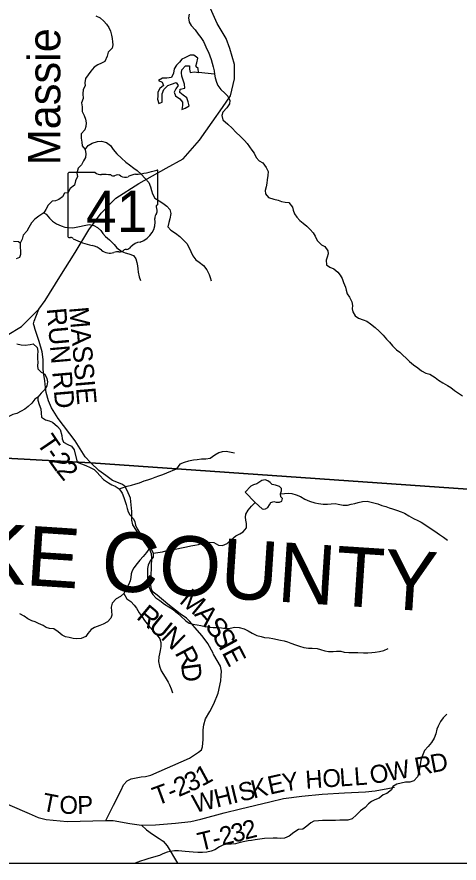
# Model space of a CAD drawing. Extents: x -139 to 835, y 0 to 440.
# Drawn here: x 426.3 to 470.9, y 185.1 to 270.4 of the extents above; entities that cross this region are included whole.
import ezdxf

# ---------------------------------------------------------------- set-up
doc = ezdxf.new("R2010")
doc.units = 0
for name, color, linetype in [('Default', 7, 'Continuous'), ('GM_X_County_Road', 7, 'Continuous'), ('GM_X_County_Road_Text', 7, 'Continuous'), ('GM_X_County_Text', 7, 'Continuous'), ('GM_X_Minor_Lake', 7, 'Continuous'), ('GM_X_Minor_River', 7, 'Continuous'), ('GM_X_Minor_River_Text', 7, 'Continuous'), ('GM_X_State_Location', 7, 'Continuous'), ('GM_X_State_Route', 7, 'Continuous'), ('GM_X_State_Shield', 7, 'Continuous'), ('GM_X_Township_Road', 7, 'Continuous'), ('GM_X_Township_Road_Text', 7, 'Continuous'), ('SH_Cut_Line', 7, 'Continuous')]:
    doc.layers.add(name, color=color, linetype=linetype)

msp = doc.modelspace()

# ---------------------------------------------------------------- linework, layer by layer
at = {"layer": 'Default'}
msp.add_lwpolyline([(373.24, 306.128), (373.24, 228.621), (390.412, 227.867), (402.968, 227.036), (407.389, 226.858), (433.728, 225.419), (479.461, 222.215), (494.743, 221.147), (512.652, 220.106), (533.705, 218.461), (553.865, 217.083)], dxfattribs=at)
msp.add_lwpolyline([(373.24, 228.621), (373.24, 185.075), (509.507, 185.075), (512.652, 220.106), (494.743, 221.147), (479.461, 222.215), (433.728, 225.419), (407.389, 226.858), (402.968, 227.036), (390.412, 227.867)], close=True, dxfattribs=at)
at = {"layer": 'GM_X_County_Road'}
msp.add_lwpolyline([(407.729, 190.508), (416.734, 193.08), (418.79, 193.617), (419.041, 193.654), (419.453, 193.54), (427.529, 190.066), (428.437, 189.666), (429.238, 189.452), (431.361, 189.276), (435.253, 189.374), (435.985, 189.354), (437.671, 189.078), (438.839, 188.895), (439.339, 188.429), (439.97, 187.993), (440.642, 187.567), (441.046, 187.285), (441.426, 186.8), (442.484, 185.075)], dxfattribs=at)
at = {"layer": 'GM_X_Minor_Lake'}
for points in [[(444.361, 265.332), (444.319, 265.378), (444.441, 265.737), (444.526, 266.204), (444.112, 266.485), (443.746, 266.489), (443.234, 266.231), (442.906, 266.102), (442.693, 265.793), (442.388, 265.484), (442.148, 265.115), (442.064, 264.684), (441.888, 264.254), (441.405, 264.188), (440.974, 264.169), (440.553, 263.957), (440.929, 263.773), (441.068, 263.436), (440.686, 263.152), (440.511, 262.758), (440.492, 262.362), (440.462, 262.063), (440.6, 261.641), (440.928, 261.769), (440.947, 262.237), (440.939, 262.585), (441.102, 263.039), (441.512, 263.442), (441.892, 263.582), (442.351, 263.745), (442.556, 263.443), (442.303, 263.109), (442.142, 262.763), (442.294, 262.39), (442.707, 262.097), (442.977, 261.746), (442.985, 261.41), (442.928, 261.015), (443.256, 261.155), (443.651, 261.39), (443.565, 261.799), (443.414, 262.209), (443.052, 262.465), (442.716, 262.745), (442.747, 263.056), (443.205, 263.183), (443.184, 263.567), (443.059, 263.965), (442.908, 264.375), (442.886, 264.699), (442.917, 265.022), (443.275, 265.414), (443.693, 265.434), (443.688, 265.074), (443.775, 264.761), (444.18, 264.804), (444.61, 264.751), (444.563, 265.148)], [(444.563, 265.148), (444.361, 265.332)], [(450.313, 221.401), (451.007, 220.778), (451.163, 220.73), (451.36, 220.79), (451.608, 220.911), (451.752, 221.187), (451.909, 221.403), (452.183, 221.511), (452.445, 221.452), (452.759, 221.464), (453.02, 221.548), (453.059, 221.813), (452.915, 221.992), (452.876, 222.293), (452.981, 222.605), (452.981, 222.833), (452.758, 223.025), (452.353, 223.144), (452.039, 223.24), (451.817, 223.42), (451.594, 223.6), (451.307, 223.696), (450.993, 223.635), (450.797, 223.503), (450.47, 223.31), (450.143, 223.178), (449.882, 223.058), (449.319, 222.469)], [(449.319, 222.469), (450.313, 221.401)]]:
    msp.add_lwpolyline(points, dxfattribs=at)
at = {"layer": 'GM_X_Minor_River'}
for points in [[(434.234, 270.473), (434.687, 270.252), (435.062, 269.936), (435.332, 269.633), (435.549, 269.294), (435.713, 268.908), (435.825, 268.499), (435.886, 268.162), (435.921, 267.85), (435.956, 267.55), (435.886, 267.214), (435.489, 266.811), (435.392, 266.392), (435.163, 265.867), (434.821, 265.679), (434.453, 265.515), (434.071, 265.28), (433.727, 264.9), (433.474, 264.519), (433.195, 264.138), (433.15, 263.707), (433.171, 263.394), (432.958, 263.037), (432.926, 262.605), (432.972, 262.137), (432.796, 261.707), (432.882, 261.298), (432.875, 260.818), (433.078, 260.408), (433.217, 260.046), (433.264, 259.662), (433.246, 259.302), (433.124, 258.979), (432.766, 258.564), (432.76, 258.144), (432.82, 257.723), (432.854, 257.363), (433.162, 256.975), (433.248, 256.554), (433.203, 256.183), (432.99, 255.861), (432.789, 255.456), (432.458, 255.1), (432.321, 254.609), (432.394, 254.26), (432.206, 253.819), (432.108, 253.4), (431.66, 253.057), (431.406, 252.628), (431.08, 252.596), (430.866, 252.214), (430.497, 251.955), (430.169, 251.827), (429.842, 251.782), (429.432, 251.379), (429.217, 250.938), (428.991, 250.604), (428.49, 250.286), (428.082, 249.967), (427.75, 249.587), (427.496, 249.134), (427.282, 248.765), (426.898, 248.349), (426.801, 247.966)], [(443.646, 270.63), (443.589, 270.246), (443.661, 269.826), (443.866, 269.475), (444.251, 269.039), (444.558, 268.603), (444.841, 268.288), (445.097, 267.889), (445.236, 267.576), (445.452, 267.117), (445.604, 266.792), (445.743, 266.43), (445.881, 266.057), (445.994, 265.695), (446.08, 265.334), (446.166, 264.902), (446.213, 264.565), (446.274, 264.216), (446.398, 263.783), (446.563, 263.445), (446.858, 263.034), (447.245, 262.67), (447.541, 262.366), (447.744, 261.92), (447.739, 261.596), (447.472, 261.191), (447.049, 260.764), (446.94, 260.429), (447.064, 259.984), (447.541, 259.547), (447.98, 259.146), (448.379, 258.733), (448.843, 258.284), (449.229, 257.896), (449.499, 257.581), (449.755, 257.242), (449.973, 256.927), (450.203, 256.613), (450.406, 256.167), (450.715, 255.839), (451.091, 255.655), (451.437, 255.183), (451.64, 254.761), (451.595, 254.353), (451.538, 253.946), (451.507, 253.586), (451.411, 253.24), (451.327, 252.857), (451.362, 252.52), (451.644, 252.145), (452.203, 251.983), (452.632, 251.882), (452.97, 251.746), (453.347, 251.682), (453.725, 251.642), (454.085, 251.182), (454.146, 250.869)], [(446.213, 264.565), (444.61, 264.751)], [(433.162, 256.975), (433.468, 257.392), (433.889, 257.627), (434.413, 257.789), (434.818, 257.82), (435.325, 257.682), (435.712, 257.378), (436.007, 257.002), (436.367, 256.542), (436.818, 256.117), (437.282, 255.728), (437.644, 255.448), (438.07, 255.119), (438.406, 254.863), (438.805, 254.499), (439.204, 254.074), (439.577, 253.65), (439.754, 253.228), (439.853, 252.855), (439.953, 252.506), (440.182, 252.095), (440.622, 251.802), (440.997, 251.57), (441.398, 251.277), (441.694, 250.938), (441.793, 250.553), (441.707, 250.014), (441.597, 249.631), (441.513, 249.212), (441.822, 248.849), (442.288, 248.568), (442.727, 248.227), (443.049, 247.899), (443.409, 247.523), (443.626, 247.149), (443.842, 246.726), (444.019, 246.28), (444.326, 245.857), (444.675, 245.625), (445.114, 245.284), (445.448, 244.872), (445.664, 244.402), (445.764, 244.077), (445.864, 243.764)], [(454.146, 250.869), (454.297, 250.495), (454.528, 250.157), (454.836, 249.829), (455.172, 249.562), (455.521, 249.27), (455.855, 248.918), (456.151, 248.591), (456.368, 248.24), (456.584, 247.818), (457.009, 247.381), (457.346, 247.198), (457.654, 246.774), (457.663, 246.462), (457.593, 246.151), (457.471, 245.828), (457.504, 245.36), (457.853, 245.116), (458.242, 244.956), (458.656, 244.639), (458.873, 244.313), (459.078, 243.987), (459.229, 243.601), (459.419, 243.131), (459.505, 242.806), (459.579, 242.445), (459.822, 242.094), (460.077, 241.636), (460.124, 241.263), (460.107, 240.939), (460.155, 240.627), (460.384, 240.228), (460.746, 239.996), (461.214, 239.835), (461.565, 239.687), (461.953, 239.431), (462.431, 239.066), (462.83, 238.677), (463.216, 238.265), (463.564, 237.889), (463.847, 237.586), (464.155, 237.211), (464.567, 236.798), (464.903, 236.555), (465.212, 236.251), (465.548, 235.959), (465.896, 235.62), (466.27, 235.304), (466.723, 234.974), (467.084, 234.671), (467.525, 234.462), (467.915, 234.337), (468.472, 234.007), (468.807, 233.728), (469.248, 233.459), (469.701, 233.19), (470.051, 232.994), (470.426, 232.714), (470.813, 232.421), (471.214, 232.153)], [(428.991, 250.604), (429.237, 250.458), (429.558, 250.082), (429.88, 249.766), (430.281, 249.51), (430.735, 249.312), (431.111, 249.176), (431.45, 249.112), (431.919, 249.107), (432.246, 249.151), (432.6, 249.243), (433.071, 249.345), (433.581, 249.423), (434.036, 249.334), (434.399, 249.126), (434.734, 248.81), (434.939, 248.508), (435.209, 248.205), (435.609, 247.888), (436.099, 247.427), (436.368, 247.076), (436.859, 246.71), (437.209, 246.574), (437.561, 246.486), (438.041, 246.3), (438.271, 245.962), (438.371, 245.613), (438.444, 245.252), (438.479, 244.952), (438.514, 244.615), (438.599, 244.158), (438.738, 243.797)], [(426.626, 247.536), (426.432, 247.671), (425.924, 247.725)], [(426.801, 247.966), (426.626, 247.536), (426.607, 247.141), (426.654, 246.732), (426.637, 246.408), (426.528, 246.098), (426.2, 245.969)], [(426.278, 237.401), (426.72, 237.312), (427.111, 237.272), (427.608, 237.35), (427.935, 237.394), (428.322, 237.042), (428.382, 236.669), (428.363, 236.273), (428.371, 235.901), (428.38, 235.553), (428.375, 235.193), (428.383, 234.869), (428.744, 234.553), (429.107, 234.333), (429.31, 233.922), (429.357, 233.574), (429.286, 233.167), (429.072, 232.785), (428.715, 232.417), (428.383, 232.013), (428.392, 231.713), (428.543, 231.291), (428.693, 230.858), (428.726, 230.401), (428.76, 230.029), (429.161, 229.736), (429.538, 229.636), (429.875, 229.512), (430.392, 229.086), (430.635, 228.771), (430.809, 228.157), (430.844, 227.833), (430.996, 227.507), (431.423, 227.25), (431.799, 227.078), (432.042, 226.715), (432.364, 225.486)], [(428.383, 232.013), (428.08, 231.837), (427.787, 231.42), (427.431, 231.1), (427.088, 230.828), (426.719, 230.604), (426.272, 230.393), (425.866, 230.278), (425.538, 230.126), (425.117, 229.915), (424.764, 229.847), (424.341, 229.48), (423.973, 229.256), (423.645, 229.104), (423.316, 228.964), (422.908, 228.656), (422.851, 228.321), (422.856, 227.805), (422.642, 227.363), (422.624, 227.015), (422.656, 226.559)], [(448.237, 226.387), (447.742, 226.501), (447.404, 226.553), (446.985, 226.509), (446.645, 226.429), (446.237, 226.182), (445.788, 225.863), (445.33, 225.784), (444.9, 225.777), (444.455, 225.722), (444.102, 225.678), (443.605, 225.588), (443.159, 225.437), (442.713, 225.262), (442.365, 224.803)], [(432.364, 225.486), (433.25, 225.142), (433.682, 224.95), (434.061, 224.723), (434.388, 224.423), (434.649, 224.123), (435.028, 223.739), (435.512, 223.391), (435.852, 223.199), (436.179, 223.044), (436.597, 222.804), (436.911, 222.36), (437.081, 221.916), (437.173, 221.616), (437.291, 221.196), (437.395, 220.812), (437.513, 220.488), (437.657, 220.175), (438.049, 219.768), (438.18, 219.468), (438.245, 219.143), (438.415, 218.747), (438.664, 218.375), (439.017, 217.968), (439.331, 217.548), (439.828, 216.756), (440.037, 216.324), (440.024, 215.904), (439.736, 215.531), (439.514, 215.087), (439.462, 214.774), (439.449, 214.39), (439.449, 214.042), (439.462, 213.658), (439.514, 213.286), (439.619, 212.877), (439.75, 212.517), (439.985, 212.133), (440.312, 211.81), (440.691, 211.534), (441.162, 211.174), (441.593, 210.898), (442.038, 210.635), (442.496, 210.275), (442.809, 209.951), (443.306, 209.495), (443.646, 209.268), (444.039, 209.136), (444.47, 209.089), (444.85, 209.017), (445.268, 208.933), (445.726, 208.85), (446.066, 208.826), (446.432, 208.803), (446.916, 208.767), (447.308, 208.732), (447.779, 208.756), (448.249, 208.841), (448.707, 208.805), (449.204, 208.686), (449.609, 208.494), (450.028, 208.231), (450.486, 208.003), (450.93, 207.895), (451.257, 207.824), (451.715, 207.776), (452.081, 207.717), (452.866, 207.55), (453.232, 207.466), (453.585, 207.358), (453.912, 207.227), (454.37, 207.071), (454.775, 206.939), (455.233, 206.808), (455.677, 206.724), (456.07, 206.737), (456.567, 206.69), (456.894, 206.594), (457.351, 206.45), (457.704, 206.391), (458.175, 206.403), (458.515, 206.44), (458.96, 206.416), (459.3, 206.345), (459.771, 206.297), (460.673, 206.298), (461.249, 206.275), (461.68, 206.276), (462.072, 206.288), (462.426, 206.337), (462.844, 206.397), (463.289, 206.494), (463.72, 206.698)], [(436.597, 222.804), (437.395, 223.045), (437.852, 223.153), (438.284, 223.286), (438.663, 223.394), (439.134, 223.587), (439.474, 223.695), (439.892, 223.84), (440.245, 223.96), (440.585, 224.092), (441.016, 224.249), (441.409, 224.405), (442.365, 224.803)], [(452.876, 222.293), (453.687, 222.366), (454.027, 222.33), (454.445, 222.198), (454.903, 222.031), (455.335, 221.755), (455.792, 221.54), (456.342, 221.384), (456.708, 221.312), (457.178, 221.253), (457.597, 221.253), (457.989, 221.29), (458.368, 221.302), (458.695, 221.231), (459.192, 221.135), (459.624, 221.16), (459.99, 221.232), (460.382, 221.305), (460.709, 221.401), (461.141, 221.498), (461.611, 221.534), (462.03, 221.439), (462.684, 221.271), (463.089, 221.128), (463.482, 221.008), (463.835, 220.889), (464.175, 220.781), (464.58, 220.637), (465.038, 220.482), (465.378, 220.35), (465.81, 220.075), (466.28, 219.787), (466.725, 219.595), (467.052, 219.416), (467.523, 219.116), (467.968, 218.841), (468.452, 218.517), (468.896, 218.194), (469.315, 217.906), (469.707, 217.618)], [(440.037, 216.324), (440.965, 216.433), (441.305, 216.529), (441.632, 216.59), (442.103, 216.686), (442.43, 216.747), (442.874, 216.831), (443.397, 216.952), (443.842, 217.036), (444.234, 217.121), (444.587, 217.193), (444.914, 217.277), (445.358, 217.386), (445.685, 217.41), (446.13, 217.387), (446.601, 217.123), (447.032, 217.088), (447.477, 217.28), (447.921, 217.701), (448.353, 218.05), (448.771, 218.266), (449.111, 218.447), (449.451, 218.867), (449.451, 219.299), (449.359, 219.623), (449.333, 219.936), (449.385, 220.248), (449.594, 220.644), (449.934, 221.053), (450.313, 221.401)], [(439.828, 216.756), (439.605, 216.72), (439.357, 216.383), (439.017, 215.974), (438.69, 215.59), (438.429, 215.253), (438.089, 214.845), (437.906, 214.521), (437.814, 214.22), (437.762, 213.848), (437.71, 213.524), (437.54, 213.103), (437.291, 212.695), (437.056, 212.25), (436.716, 211.95), (436.285, 211.709), (435.879, 211.252), (435.788, 210.856), (435.814, 210.46), (435.853, 210.064), (435.762, 209.751), (435.435, 209.379), (434.977, 209.15), (434.637, 209.018), (434.114, 208.801), (433.761, 208.608), (433.447, 208.224), (433.225, 207.923), (432.78, 207.695), (432.27, 207.682), (431.944, 207.718), (431.538, 207.801), (431.198, 207.885), (430.858, 208.029), (430.453, 208.377), (430.022, 208.676), (429.577, 208.724), (429.25, 208.832), (428.923, 209.011), (428.466, 209.203), (428.139, 209.371), (427.799, 209.491), (427.394, 209.682), (427.001, 209.946), (426.583, 210.198)], [(437.056, 212.25), (437.37, 211.722), (437.775, 211.447), (438.115, 211.063), (438.338, 210.751), (438.625, 210.295), (438.913, 209.875), (439.148, 209.527), (439.41, 209.179), (439.645, 208.879), (440.051, 208.459), (440.417, 208.051), (440.691, 207.679), (440.809, 207.295), (440.783, 206.899), (440.718, 206.515), (440.652, 206.167), (440.6, 205.854), (440.574, 205.398), (440.665, 204.918), (440.835, 204.462), (441.058, 204.09), (441.345, 203.646), (441.541, 203.322), (441.685, 203.022), (441.842, 202.65), (441.96, 202.242)], [(469.633, 200.079), (469.266, 199.718), (469.018, 199.345), (468.757, 198.889), (468.639, 198.576), (468.521, 198.084), (468.377, 197.652), (468.103, 197.219), (467.763, 196.835), (467.41, 196.414), (467.253, 196.077), (467.122, 195.753), (467.031, 195.453), (466.952, 194.984), (466.9, 194.564), (466.835, 194.204), (466.678, 193.759), (466.312, 193.363), (465.906, 193.23), (465.488, 193.242), (465.03, 193.133), (464.611, 193.012), (464.193, 192.784), (464.049, 192.459), (463.591, 192.098), (463.225, 191.942), (462.807, 191.629), (462.388, 191.436), (462.061, 191.28), (461.734, 191.051), (461.42, 190.691), (460.937, 190.33), (460.531, 189.945), (460.087, 189.548), (459.655, 189.416), (459.263, 189.403), (458.857, 189.391), (458.412, 189.378), (457.118, 189.376), (456.699, 189.34), (456.241, 189.291), (455.915, 189.135), (455.535, 188.786), (455.117, 188.497), (454.698, 188.461), (454.227, 188.16), (453.744, 187.787), (453.286, 187.594), (452.867, 187.558), (452.527, 187.581), (452.135, 187.593), (451.246, 187.544), (450.801, 187.483), (450.304, 187.41), (449.938, 187.35), (449.611, 187.301), (449.258, 187.241), (448.787, 187.144), (448.329, 187.023), (447.898, 186.987), (447.571, 186.974), (447.113, 186.926), (446.72, 186.697), (446.237, 186.408), (445.883, 186.264), (445.452, 186.179), (444.994, 186.155), (444.523, 186.142), (444.066, 186.177), (443.255, 186.248), (442.928, 186.272), (442.575, 186.295), (442.195, 186.307), (441.751, 186.258), (441.424, 186.186), (441.018, 186.017), (440.652, 185.849), (440.312, 185.74), (439.959, 185.644), (439.606, 185.535), (439.174, 185.391), (438.756, 185.27), (438.377, 185.125), (438.217, 185.075)]]:
    msp.add_lwpolyline(points, dxfattribs=at)
at = {"layer": 'GM_X_State_Route'}
msp.add_lwpolyline([(425.292, 238.291), (426.736, 239.16), (428.491, 240.911), (429.145, 241.765), (430.624, 244.159), (432.156, 246.601), (433.544, 248.899), (434.77, 250.586), (436.257, 252.079), (438.567, 253.569), (441.335, 255.116), (443.066, 256.056), (444.713, 257.945), (445.966, 259.728), (447.009, 261.236), (447.814, 262.385), (448.244, 264.1), (448.228, 265.565), (447.755, 267.165), (447.383, 268.187), (446.478, 269.681), (445.666, 271.498)], dxfattribs=at)
at = {"layer": 'GM_X_State_Shield'}
for p, q in [((431.426, 254.546), (431.426, 248.219)), ((434.177, 254.655), (431.516, 254.655)), ((440.513, 251.502), (440.513, 254.812)), ((440.513, 251.503), (440.513, 251.502))]:
    msp.add_line(p, q, dxfattribs=at)
for centre, major_axis, start_param, end_param in [((431.53, 254.56), (0.105, 0), 1.712693, 3.28349), ((434.811, 255.39), (1.021, 0), 4.042523, 4.731795), ((435.149, 251.103), (3.666, 0), 1.404758, 1.657858), ((435.982, 254.593), (0.295, 0), 3.836095, 5.185415), ((436.414, 253.861), (0.612, 0), 0.950623, 2.079405), ((437.204, 254.864), (0.737, 0), 4.081561, 5.145723), ((438.506, 252.723), (1.939, 0), 1.699011, 2.107814), ((437.276, 263.282), (9.637, 0), 4.814394, 5.042369), ((440.413, 254.826), (0.101, 0), 6.141152, 7.989035), ((440.49, 251.259), (0.157, 0), 1.883978, 3.671073), ((439.494, 250.841), (0.94, 0), 5.934695, 6.695948), ((440.405, 251.489), (0.108, 0), 5.05454, 6.418171), ((437.816, 249.696), (2.41, 0), 5.101752, 6.440018), ((440.876, 250.117), (0.684, 0), 2.387724, 3.262537), ((431.531, 248.205), (0.106, 0), 3.00124, 4.508301), ((431.548, 248.852), (0.81, 0), 4.665946, 4.897461), ((431.713, 247.854), (0.292, 0), 0.519207, 1.627899), ((435.403, 253.539), (6.959, 0), 4.195997, 4.488961), ((433.328, 245.376), (2.177, 0), 0.823519, 1.323587), ((438.833, 246.442), (1.32, 0), 1.647645, 2.488434), ((435.683, 247.822), (1.382, 0), 4.026481, 4.996735), ((436.482, 245.635), (1.135, 0), 1.495662, 1.94098), ((436.583, 247.349), (0.736, 0), 4.691044, 5.507374), ((437.248, 246.736), (0.207, 0), 1.147584, 2.315152), ((437.16, 247.606), (0.779, 0), 4.937069, 5.64225)]:
    msp.add_ellipse(centre, major_axis=major_axis, ratio=0.917426, start_param=start_param, end_param=end_param, dxfattribs=at)
at = {"layer": 'GM_X_Township_Road'}
for points in [[(433.736, 225.402), (433.173, 226.003), (432.144, 227.615), (430.455, 229.893), (429.779, 230.94), (429.459, 231.644), (429.222, 232.513), (429.158, 233.019), (429.111, 233.68), (428.977, 234.499), (428.923, 234.896), (428.922, 235.82), (428.839, 236.59), (428.53, 237.653), (428.119, 238.85), (428.011, 239.213), (427.965, 239.43), (428.037, 239.68), (428.491, 240.911)], [(446.123, 206.11), (446.065, 206.22), (445.544, 207.211), (444.969, 207.982), (444.228, 208.831), (443.723, 209.43), (443.372, 209.746), (442.741, 210.182), (441.51, 211.173), (440.444, 212.072), (440.041, 212.378), (439.872, 212.65), (439.803, 213.086), (439.881, 215.848), (439.861, 216.234), (439.675, 216.675), (439.187, 217.369), (438.335, 218.597), (437.985, 219.177), (437.878, 219.626), (437.871, 220.516), (437.742, 221.865), (437.406, 222.639), (437.163, 223.074), (436.874, 223.265), (435.926, 223.626), (435.244, 224.125), (434.561, 224.655), (433.736, 225.402)], [(435.253, 189.374), (436.025, 190.904), (436.797, 192.41), (437.049, 192.977), (437.409, 193.37), (437.799, 193.57), (438.803, 193.755), (439.263, 193.796), (439.794, 193.942), (443.677, 195.639), (444.584, 196.237), (444.898, 196.477), (444.993, 196.797), (445.057, 197.528), (445.055, 198.502), (445.121, 199.016), (445.308, 199.609), (445.738, 200.337), (446.133, 201.126), (446.568, 202.201), (446.84, 203.428), (446.882, 203.979), (446.917, 204.399), (446.813, 204.92), (446.152, 206.055), (446.123, 206.11)], [(438.839, 188.895), (440.255, 188.943), (442.291, 189.096), (443.818, 189.271), (444.838, 189.504), (447.187, 190.149), (448.831, 190.547), (451.799, 191.262), (453.189, 191.575), (455.021, 191.833), (457.072, 192.022), (459.316, 192.142), (461.455, 192.255), (462.402, 192.347), (463.696, 192.58), (464.381, 192.714)]]:
    msp.add_lwpolyline(points, dxfattribs=at)
at = {"layer": 'SH_Cut_Line'}
for points in [[(607.596, 213.413), (607.596, 400.079), (373.24, 400.079), (373.24, 228.621), (390.412, 227.867), (402.968, 227.036), (407.389, 226.858), (433.728, 225.419), (479.461, 222.215), (494.743, 221.147), (512.652, 220.106), (533.705, 218.461), (553.865, 217.083)], [(373.24, 228.621), (373.24, 185.075), (607.596, 185.075), (607.596, 213.413), (553.865, 217.083), (533.705, 218.461), (512.652, 220.106), (494.743, 221.147), (479.461, 222.215), (433.728, 225.419), (407.389, 226.858), (402.968, 227.036), (390.412, 227.867)]]:
    msp.add_lwpolyline(points, close=True, dxfattribs=at)

# ---------------------------------------------------------------- texts
at = {"layer": 'GM_X_County_Road_Text'}
for s, height, rotation, p in [('T', 1.826, 348.74967, (428.717, 190.381)), ('O', 1.797, 358.95312, (430.559, 190.053)), ('P', 1.797, 1.81384, (432.398, 190.022))]:
    msp.add_text(s, height=height, rotation=rotation, dxfattribs=at).set_placement(p)
at = {"layer": 'GM_X_County_Text'}
msp.add_text('PIKE COUNTY', height=6.00014, rotation=356.27066, dxfattribs=at).set_placement((414.193, 213.934))
at = {"layer": 'GM_X_Minor_River_Text'}
msp.add_text('Massie', height=3.2631, rotation=90.01065, dxfattribs=at).set_placement((430.66, 255.394))
at = {"layer": 'GM_X_State_Location'}
for s, p in [('s', (435.868, 250.962)), ('r', (435.867, 250.962))]:
    msp.add_text(s, height=0.00599, dxfattribs=at).set_placement(p)
msp.add_text('41', height=0.00599, rotation=0.00001, dxfattribs=at).set_placement((434.224, 250.526))
at = {"layer": 'GM_X_State_Shield'}
msp.add_text('41', height=4.1684, dxfattribs=at).set_placement((433.243, 248.665))
at = {"layer": 'GM_X_Township_Road_Text'}
for s, height, rotation, p in [('RUN RD', 1.9592, 274.99169, (429.286, 240.96)), ('MASSIE', 1.9591, 274.88656, (431.549, 241.071)), ('T', 1.985, 304.10369, (428.206, 227.425)), ('2', 1.985, 305.38027, (429.431, 225.623)), ('-', 1.985, 304.35907, (428.984, 226.276)), ('2', 1.985, 308.72219, (430.158, 224.604)), ('M', 1.97, 320.23118, (442.574, 211.363)), ('R', 1.97, 320.21884, (438.242, 209.763)), ('A', 1.984, 311.60755, (444.095, 210.105)), ('U', 1.968, 320.83388, (439.45, 208.757)), ('S', 1.985, 308.7409, (445.168, 208.897)), ('N', 1.979, 315.78308, (440.706, 207.737)), ('S', 1.983, 301.89568, (445.918, 207.967)), ('I', 1.981, 298.91679, (446.561, 206.936)), ('R', 1.98, 297.94461, (442.167, 206.266)), ('E', 1.98, 297.38677, (446.919, 206.288)), ('D', 1.96, 277.57958, (442.822, 205.09)), ('D', 1.824, 10.78643, (468.158, 194.154)), ('W', 1.824, 10.78622, (463.771, 193.318)), ('R', 1.824, 10.78738, (466.583, 193.854)), ('1', 1.926, 28.48651, (444.942, 192.754)), ('H', 1.801, 3.9921, (455.438, 192.563)), ('O', 1.8, 3.76069, (457.154, 192.683)), ('L', 1.8, 3.76985, (458.873, 192.795)), ('L', 1.801, 4.03669, (460.345, 192.893)), ('O', 1.819, 9.62755, (462.03, 193.023)), ('2', 1.898, 23.49977, (442.596, 191.71)), ('3', 1.902, 24.18666, (443.711, 192.195)), ('K', 1.839, 13.69543, (450.14, 191.559)), ('E', 1.833, 12.56841, (451.795, 191.962)), ('Y', 1.813, 8.1098, (453.175, 192.272)), ('T', 1.877, 20.15089, (440.388, 190.847)), ('H', 1.839, 13.73087, (446.422, 190.65)), ('I', 1.839, 13.72996, (448.087, 191.057)), ('S', 1.839, 13.72933, (448.864, 191.247)), ('-', 1.897, 23.44435, (441.867, 191.394)), ('W', 1.839, 13.73102, (444.229, 190.115)), ('2', 1.843, 14.32961, (449.309, 187.417)), ('2', 1.842, 14.24301, (446.981, 186.825)), ('3', 1.843, 14.30656, (448.146, 187.12)), ('T', 1.838, 13.55042, (444.761, 186.282)), ('-', 1.842, 14.11457, (446.2, 186.628))]:
    msp.add_text(s, height=height, rotation=rotation, dxfattribs=at).set_placement(p)

doc.saveas('drawing.dxf')
